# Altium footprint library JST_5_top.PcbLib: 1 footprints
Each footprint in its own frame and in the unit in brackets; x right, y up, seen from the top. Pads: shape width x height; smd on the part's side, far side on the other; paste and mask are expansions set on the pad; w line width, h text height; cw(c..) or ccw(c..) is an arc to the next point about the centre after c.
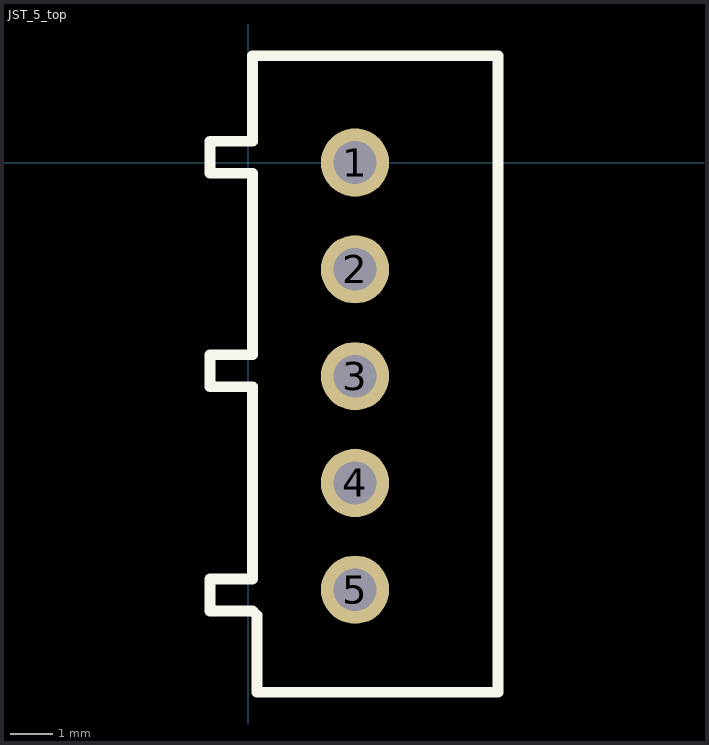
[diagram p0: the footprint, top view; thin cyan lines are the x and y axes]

## JST_5_top [mm]
pads (5):
  round 1.6 hole 1: 1(2.5,0) 2(2.5,-2.5) 3(2.5,-5) 4(2.5,-7.5) 5(2.5,-10)
Top Overlay:
  lines w0.254: 0.1,0.5 -0.9,0.5 -0.9,-0.25 0.1,-0.25 0.1,-4.5 -0.9,-4.5 -0.9,-5.25 0.1,-5.25 0.1,-9.75 -0.9,-9.75 -0.9,-10.5 0.1,-10.5 0.2,-10.6 0.2,-12.4 5.85,-12.4 5.85,2.5 0.1,2.5 0.1,0.5 ; 0.1,0.5 0.1,0.5
3D body: height 7, standoff 0, extent -1.027,-12.527 5.977,2.627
